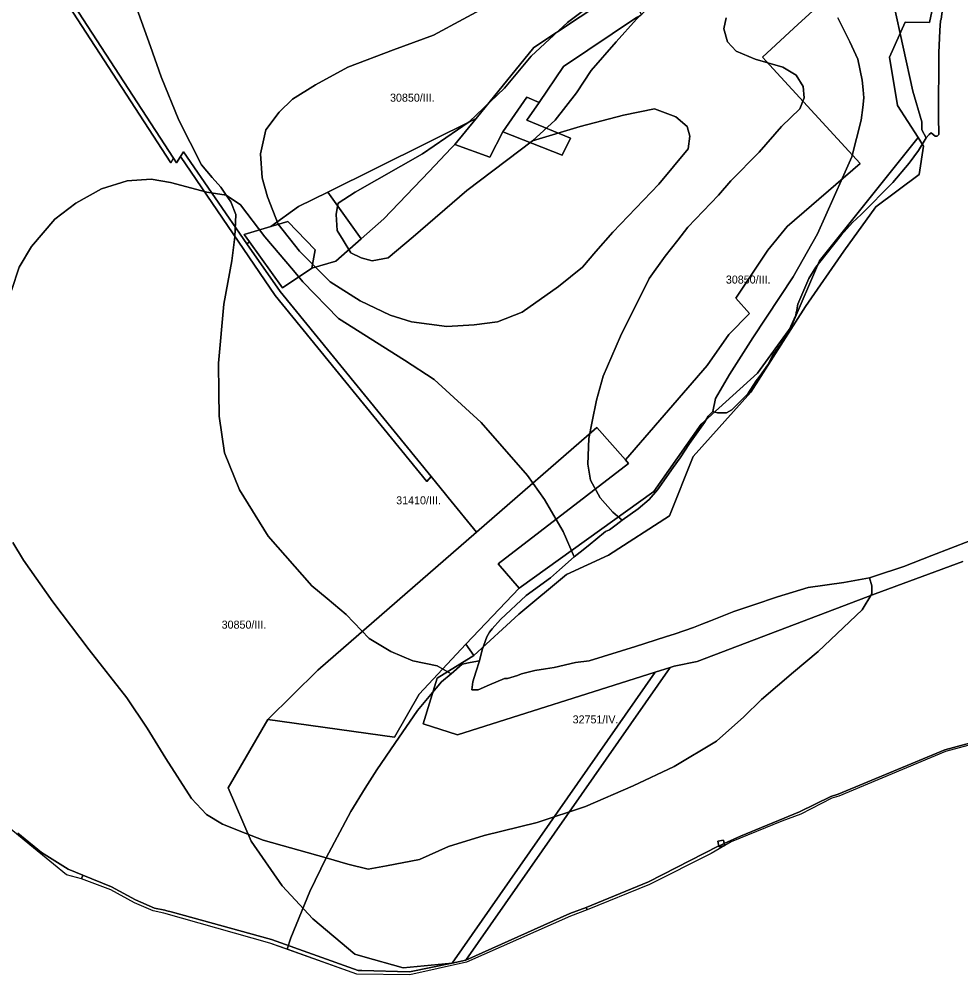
# Model space of a CAD drawing. Extents: x -541351 to -537540, y -1162694 to -1159725.
# Drawn here: x -538870 to -538281, y -1162694 to -1162097 of the extents above; entities that cross this region are included whole.
import ezdxf

# ---------------------------------------------------------------- set-up
doc = ezdxf.new("R2010")
doc.units = 0
for name, color, linetype in [('95560013', 7, 'Continuous'), ('95610013', 7, 'Continuous'), ('95620013', 7, 'Continuous'), ('95640013', 7, 'Continuous'), ('95660013', 7, 'Continuous')]:
    doc.layers.add(name, color=color, linetype=linetype)

msp = doc.modelspace()

# ---------------------------------------------------------------- linework, layer by layer
at = {"layer": '95560013'}
for points in [[(-538869.43, -1162041.03), (-538774.88, -1162186.74), (-538773.11, -1162183.87), (-538771.26, -1162186.72), (-538768.78, -1162182.83), (-538709.7, -1162269.66), (-538614.93, -1162385.76), (-538612.14, -1162382.82), (-538603.16, -1162393.83), (-538601.47, -1162395.9), (-538583.87, -1162417.45), (-538683.04, -1162503.68), (-538714.23, -1162534.51), (-538739.09, -1162577.31), (-538724.64, -1162610.63), (-538705.36, -1162638.6), (-538686.21, -1162659.05), (-538659.93, -1162681.21), (-538654.86, -1162682.65), (-538629.62, -1162689.8), (-538598.98, -1162686.73), (-538625.63, -1162692.31), (-538655.54, -1162691.51), (-538657.71, -1162691.45), (-538711.99, -1162672), (-538774.67, -1162654.78), (-538777.4, -1162654.03), (-538778.52, -1162653.72), (-538785.14, -1162652.4), (-538796.95, -1162647.2), (-538811.97, -1162639.05), (-538829.93, -1162631.77), (-538838.99, -1162628.1), (-538855.65, -1162617.58), (-538870.45, -1162605.67)], [(-538490.13, -1162076.14), (-538547.99, -1162114.54), (-538584.08, -1162158.95), (-538676.75, -1162205), (-538695.05, -1162214.09), (-538712.27, -1162226.46), (-538729.02, -1162231.4), (-538725.68, -1162236.09), (-538727.27, -1162237.23), (-538766.94, -1162179.94), (-538768.78, -1162182.83), (-538771.26, -1162186.72), (-538773.11, -1162183.87), (-538866.22, -1162040.39)], [(-538358.33, -1162077.66), (-538382.75, -1162100.13), (-538405.09, -1162120.69), (-538402.82, -1162123.17), (-538400.74, -1162125.44), (-538344.11, -1162187.17), (-538389.74, -1162226.5), (-538401.72, -1162241.28), (-538421.82, -1162271.38), (-538413.32, -1162280.83), (-538426.13, -1162294.07), (-538439.64, -1162313.45), (-538490.74, -1162372.39), (-538508.66, -1162352.04), (-538583.87, -1162417.45), (-538601.47, -1162395.9), (-538603.16, -1162393.83), (-538612.14, -1162382.82), (-538706.58, -1162267.12), (-538727.27, -1162237.23), (-538725.68, -1162236.09), (-538705.15, -1162264.89), (-538686.77, -1162252.58), (-538671.71, -1162248.06), (-538655.83, -1162234.14), (-538641.65, -1162221.7), (-538613.46, -1162192.15), (-538599.58, -1162177.6), (-538597.29, -1162175.19), (-538575.5, -1162183.26), (-538567.4, -1162167.24), (-538530.37, -1162181.9), (-538525.16, -1162171.29), (-538552.35, -1162160.1), (-538544.72, -1162148.92), (-538529.45, -1162126.6), (-538483.95, -1162095.95)], [(-538257.12, -1162544.31), (-538291.24, -1162553.47), (-538357.78, -1162581.24), (-538362.41, -1162582.63), (-538381.99, -1162592.28), (-538418.76, -1162607.46), (-538428.99, -1162612.1), (-538429.43, -1162610), (-538432.98, -1162610.67), (-538432.4, -1162613.64), (-538432.73, -1162613.79), (-538476.34, -1162636.06), (-538515.25, -1162652.09), (-538525.45, -1162655.75), (-538590.41, -1162684.93), (-538462.84, -1162502), (-538460.21, -1162501.17), (-538445.95, -1162498.39), (-538334.63, -1162456.04), (-538279.83, -1162435.82)]]:
    msp.add_lwpolyline(points, dxfattribs=at)
msp.add_lwpolyline([(-538432.4, -1162613.64), (-538432.98, -1162610.67), (-538429.43, -1162610), (-538428.99, -1162612.1)], close=True, dxfattribs=at)
at = {"layer": '95610013'}
msp.add_lwpolyline([(-538294.68, -1162070.18), (-538300.82, -1162098.99), (-538315.9, -1162098.85), (-538325.79, -1162120.61), (-538320.79, -1162150.88), (-538307.92, -1162170.92), (-538369.57, -1162247.97), (-538387.23, -1162289.19), (-538408.16, -1162318.09), (-538443.36, -1162349.97), (-538473.08, -1162392.14), (-538557.2, -1162452.57), (-538570.19, -1162437.29), (-538488.91, -1162374.62), (-538490.74, -1162372.39), (-538439.64, -1162313.45), (-538426.13, -1162294.07), (-538413.32, -1162280.83), (-538421.82, -1162271.38), (-538401.72, -1162241.28), (-538389.74, -1162226.5), (-538344.11, -1162187.17), (-538400.74, -1162125.44), (-538402.82, -1162123.17), (-538405.09, -1162120.69), (-538382.75, -1162100.13), (-538358.33, -1162077.66)], dxfattribs=at)
for points in [[(-538483.95, -1162095.95), (-538529.45, -1162126.6), (-538544.72, -1162148.92), (-538552.35, -1162145.62), (-538567.4, -1162167.24), (-538575.5, -1162183.26), (-538597.29, -1162175.19), (-538584.08, -1162158.95), (-538547.99, -1162114.54), (-538490.13, -1162076.14), (-538490, -1162076.05), (-538480.64, -1162094.32)], [(-538525.16, -1162171.29), (-538530.37, -1162181.9), (-538567.4, -1162167.24), (-538552.35, -1162145.62), (-538544.72, -1162148.92), (-538552.35, -1162160.1)], [(-538684.56, -1162241), (-538701.7, -1162223.35), (-538712.27, -1162226.46), (-538695.05, -1162214.09), (-538676.75, -1162205), (-538655.83, -1162234.14), (-538671.71, -1162248.06), (-538686.77, -1162252.58)], [(-538701.7, -1162223.35), (-538684.56, -1162241), (-538686.77, -1162252.58), (-538705.15, -1162264.89), (-538725.68, -1162236.09), (-538729.02, -1162231.4), (-538712.27, -1162226.46)], [(-538714.23, -1162534.51), (-538683.04, -1162503.68), (-538583.87, -1162417.45), (-538508.66, -1162352.04), (-538490.74, -1162372.39), (-538488.91, -1162374.62), (-538570.19, -1162437.29), (-538557.2, -1162452.57), (-538590.57, -1162487.53), (-538605.03, -1162503.02), (-538619.65, -1162518.68), (-538635.07, -1162545.65)], [(-538608.47, -1162508.72), (-538617.07, -1162537.21), (-538595.65, -1162544.21), (-538472.23, -1162504.99), (-538598.98, -1162686.73), (-538629.62, -1162689.8), (-538654.86, -1162682.65), (-538659.93, -1162681.21), (-538686.21, -1162659.05), (-538705.36, -1162638.6), (-538724.64, -1162610.63), (-538739.09, -1162577.31), (-538714.23, -1162534.51), (-538635.07, -1162545.65), (-538619.65, -1162518.68), (-538605.03, -1162503.02), (-538590.57, -1162487.53), (-538585.52, -1162494.51), (-538587.16, -1162495.52)]]:
    msp.add_lwpolyline(points, close=True, dxfattribs=at)
at = {"layer": '95620013'}
msp.add_lwpolyline([(-538279.83, -1162435.82), (-538334.63, -1162456.04), (-538445.95, -1162498.39), (-538460.21, -1162501.17), (-538462.84, -1162502), (-538472.23, -1162504.99), (-538595.65, -1162544.21), (-538617.07, -1162537.21), (-538608.47, -1162508.72), (-538587.16, -1162495.52), (-538585.52, -1162494.51), (-538557.31, -1162468.81), (-538527.65, -1162443.97), (-538501.37, -1162431.85), (-538463.24, -1162407.26), (-538448.5, -1162370.31), (-538412.3, -1162330.08), (-538378.23, -1162276.57), (-538354.34, -1162241.81), (-538334.23, -1162214.24), (-538307.2, -1162193.94), (-538304.48, -1162176.27), (-538307.92, -1162170.92), (-538320.79, -1162150.88), (-538325.79, -1162120.61), (-538315.9, -1162098.85), (-538300.82, -1162098.99), (-538294.68, -1162070.18)], dxfattribs=at)
for points in [[(-538584.08, -1162158.95), (-538597.29, -1162175.19), (-538599.58, -1162177.6), (-538613.46, -1162192.15), (-538641.65, -1162221.7), (-538655.83, -1162234.14), (-538676.75, -1162205)], [(-538557.31, -1162468.81), (-538585.52, -1162494.51), (-538590.57, -1162487.53), (-538557.2, -1162452.57), (-538473.08, -1162392.14), (-538443.36, -1162349.97), (-538408.16, -1162318.09), (-538387.23, -1162289.19), (-538369.57, -1162247.97), (-538307.92, -1162170.92), (-538304.48, -1162176.27), (-538307.2, -1162193.94), (-538334.23, -1162214.24), (-538354.34, -1162241.81), (-538378.23, -1162276.57), (-538412.3, -1162330.08), (-538448.5, -1162370.31), (-538463.24, -1162407.26), (-538501.37, -1162431.85), (-538527.65, -1162443.97)]]:
    msp.add_lwpolyline(points, close=True, dxfattribs=at)
at = {"layer": '95640013'}
for points in [[(-538774.88, -1162186.74), (-538869.43, -1162041.03), (-538866.22, -1162040.39), (-538773.11, -1162183.87)], [(-538706.58, -1162267.12), (-538612.14, -1162382.82), (-538614.93, -1162385.76), (-538709.7, -1162269.66), (-538768.78, -1162182.83), (-538766.94, -1162179.94), (-538727.27, -1162237.23)], [(-538462.84, -1162502), (-538590.41, -1162684.93), (-538598.98, -1162686.73), (-538472.23, -1162504.99)], [(-538432.4, -1162613.64), (-538432.29, -1162614.22), (-538428.73, -1162613.36), (-538432.09, -1162615.33), (-538437.2, -1162618.34), (-538475.64, -1162637.57), (-538514.72, -1162653.42), (-538515.25, -1162652.09), (-538476.34, -1162636.06), (-538432.73, -1162613.79)], [(-538428.99, -1162612.1), (-538428.73, -1162613.36), (-538432.29, -1162614.22), (-538432.4, -1162613.64)], [(-538514.72, -1162653.42), (-538525.11, -1162657.36), (-538589.99, -1162686.16), (-538625.49, -1162694.15), (-538658.52, -1162693.62), (-538712.88, -1162674.25), (-538779.19, -1162655.51), (-538785.91, -1162654.22), (-538797.48, -1162649.16), (-538812.4, -1162640.97), (-538830.6, -1162634.06), (-538829.93, -1162631.77), (-538811.97, -1162639.05), (-538796.95, -1162647.2), (-538785.14, -1162652.4), (-538778.52, -1162653.72), (-538777.4, -1162654.03), (-538774.67, -1162654.78), (-538711.99, -1162672), (-538657.71, -1162691.45), (-538655.54, -1162691.51), (-538625.63, -1162692.31), (-538598.98, -1162686.73), (-538590.41, -1162684.93), (-538525.45, -1162655.75), (-538515.25, -1162652.09)]]:
    msp.add_lwpolyline(points, close=True, dxfattribs=at)
for points in [[(-538256.67, -1162545.39), (-538290.71, -1162554.65), (-538357.43, -1162582.44), (-538361.85, -1162583.75), (-538381.21, -1162593.74), (-538393.08, -1162598.16), (-538424.63, -1162610.94), (-538428.73, -1162613.36), (-538428.99, -1162612.1), (-538418.76, -1162607.46), (-538381.99, -1162592.28), (-538362.41, -1162582.63), (-538357.78, -1162581.24), (-538291.24, -1162553.47), (-538257.12, -1162544.31)], [(-538870.45, -1162605.67), (-538855.65, -1162617.58), (-538838.99, -1162628.1), (-538829.93, -1162631.77), (-538830.6, -1162634.06), (-538840.06, -1162631.57), (-538848.15, -1162624.99), (-538862.99, -1162612.9), (-538874.92, -1162603.19)]]:
    msp.add_lwpolyline(points, dxfattribs=at)
at = {"layer": '95660013'}
for points in [[(-538485.62, -1162068), (-538526.87, -1162099), (-538549.69, -1162120), (-538566.31, -1162140), (-538588.5, -1162161), (-538617.5, -1162181), (-538659.69, -1162205), (-538670.19, -1162212), (-538670.83, -1162215.11), (-538671.62, -1162219), (-538670.81, -1162229), (-538667.12, -1162235), (-538662.31, -1162243), (-538655.87, -1162246), (-538649.12, -1162248), (-538639.12, -1162246), (-538623.37, -1162233), (-538589.87, -1162204), (-538548.81, -1162173), (-538519.12, -1162164), (-538492, -1162157), (-538472.62, -1162153), (-538459.37, -1162158), (-538452.12, -1162164), (-538450.5, -1162170), (-538451.62, -1162178), (-538469.87, -1162200), (-538498.62, -1162230), (-538509.21, -1162242.22), (-538517.69, -1162252), (-538532.62, -1162264), (-538555.31, -1162280), (-538570.81, -1162286), (-538585.19, -1162288), (-538602.37, -1162289), (-538624.5, -1162286), (-538637.81, -1162282), (-538656.62, -1162273), (-538675.37, -1162261), (-538694.5, -1162242), (-538707.81, -1162225), (-538714.37, -1162208), (-538717.81, -1162196), (-538718.81, -1162181), (-538715.5, -1162166), (-538707.19, -1162155), (-538698.87, -1162147), (-538684.5, -1162138), (-538664.31, -1162127), (-538635.62, -1162116), (-538610.69, -1162107), (-538573.62, -1162087)], [(-538468.19, -1162082), (-538483.81, -1162097), (-538496.62, -1162111), (-538512.12, -1162129), (-538521.31, -1162143), (-538534.62, -1162160), (-538548.81, -1162173), (-538589.87, -1162204), (-538623.37, -1162233), (-538639.12, -1162246), (-538649.12, -1162248), (-538655.87, -1162246), (-538662.31, -1162243), (-538667.12, -1162235), (-538670.81, -1162229), (-538671.62, -1162219), (-538670.83, -1162215.11), (-538670.19, -1162212), (-538659.69, -1162205), (-538617.5, -1162181), (-538588.5, -1162161), (-538566.31, -1162140), (-538549.69, -1162120), (-538526.87, -1162099), (-538485.62, -1162068)], [(-538573.62, -1162087), (-538610.69, -1162107), (-538635.62, -1162116), (-538664.31, -1162127), (-538684.5, -1162138), (-538698.87, -1162147), (-538707.19, -1162155), (-538715.5, -1162166), (-538718.81, -1162181), (-538717.81, -1162196), (-538714.37, -1162208), (-538707.81, -1162225), (-538694.5, -1162242), (-538675.37, -1162261), (-538656.62, -1162273), (-538637.81, -1162282), (-538624.5, -1162286), (-538602.37, -1162289), (-538585.19, -1162288), (-538570.81, -1162286), (-538555.31, -1162280), (-538532.62, -1162264), (-538517.69, -1162252), (-538509.21, -1162242.22), (-538498.62, -1162230), (-538469.87, -1162200), (-538451.62, -1162178), (-538450.5, -1162170), (-538452.12, -1162164), (-538459.37, -1162158), (-538472.62, -1162153), (-538492, -1162157), (-538519.12, -1162164), (-538548.81, -1162173), (-538534.62, -1162160), (-538521.31, -1162143), (-538512.12, -1162129), (-538496.62, -1162111), (-538483.81, -1162097), (-538468.19, -1162082)], [(-538797, -1162088), (-538787.62, -1162114), (-538780.87, -1162133), (-538769.87, -1162160), (-538755.62, -1162188), (-538748.99, -1162195.78), (-538743.69, -1162202), (-538740.31, -1162207), (-538752.31, -1162205), (-538775, -1162199), (-538787.19, -1162197), (-538802.12, -1162198), (-538818.12, -1162203), (-538834.19, -1162212), (-538847.37, -1162222), (-538861.87, -1162239), (-538869.62, -1162252), (-538874.38, -1162266.44)], [(-538427.81, -1162096), (-538429.31, -1162103), (-538427, -1162111), (-538421.62, -1162117), (-538409.62, -1162122), (-538392.31, -1162127), (-538384.12, -1162132), (-538379.62, -1162139), (-538379.12, -1162146), (-538381.87, -1162153), (-538393.31, -1162164), (-538407.19, -1162180), (-538425, -1162198), (-538432.69, -1162207), (-538451.69, -1162227), (-538457.99, -1162235), (-538465.87, -1162245), (-538476, -1162259), (-538493.87, -1162295), (-538504.62, -1162320), (-538508.87, -1162335), (-538511.55, -1162348.33), (-538513.69, -1162359), (-538514.31, -1162375), (-538512.62, -1162385), (-538506.62, -1162396), (-538498.62, -1162405), (-538492.87, -1162410), (-538496.62, -1162413), (-538500.69, -1162416), (-538503.12, -1162417), (-538509.31, -1162422), (-538512.81, -1162425), (-538514, -1162426), (-538519, -1162430), (-538522.87, -1162433), (-538529.62, -1162417), (-538541.31, -1162397), (-538551.87, -1162382), (-538580.87, -1162349), (-538610.37, -1162322), (-538628.87, -1162310), (-538670.12, -1162284), (-538692.37, -1162261), (-538698.12, -1162254), (-538716, -1162233), (-538731.31, -1162213), (-538740.31, -1162207), (-538743.69, -1162202), (-538748.99, -1162195.78), (-538755.62, -1162188), (-538769.87, -1162160), (-538780.87, -1162133), (-538787.62, -1162114), (-538797, -1162088)], [(-538275.5, -1162423), (-538299.37, -1162432), (-538316.81, -1162439), (-538335.12, -1162445), (-538338.31, -1162446), (-538354.31, -1162449), (-538376.62, -1162452), (-538395.81, -1162458), (-538410.5, -1162463), (-538423, -1162467), (-538437.62, -1162473), (-538443.12, -1162475), (-538448.31, -1162477), (-538459.62, -1162481), (-538465.81, -1162483), (-538484.37, -1162489), (-538513.37, -1162498), (-538521.87, -1162499), (-538535.31, -1162502), (-538540.81, -1162503), (-538547.37, -1162504), (-538555.62, -1162506), (-538558.12, -1162507), (-538564.37, -1162509), (-538566.37, -1162509), (-538575.81, -1162513), (-538582.87, -1162516), (-538584.69, -1162516), (-538586.81, -1162516), (-538586.12, -1162511), (-538584.31, -1162505), (-538581.87, -1162498), (-538580.37, -1162491), (-538577.37, -1162483), (-538575.62, -1162480), (-538574.12, -1162478), (-538568.87, -1162472), (-538552.81, -1162457), (-538537.69, -1162446), (-538532, -1162441), (-538522.87, -1162433), (-538519, -1162430), (-538514, -1162426), (-538512.81, -1162425), (-538509.31, -1162422), (-538503.12, -1162417), (-538500.69, -1162416), (-538496.62, -1162413), (-538492.87, -1162410), (-538482.87, -1162403), (-538476, -1162397), (-538470.81, -1162391), (-538460.87, -1162377), (-538456.5, -1162371), (-538450.69, -1162362), (-538446.55, -1162356.22), (-538441.37, -1162349), (-538439.12, -1162345), (-538436.19, -1162342), (-538433.31, -1162343), (-538430.12, -1162343), (-538427.62, -1162343), (-538424.31, -1162341), (-538414.37, -1162331), (-538409, -1162323), (-538406.69, -1162320), (-538401.81, -1162313), (-538398.69, -1162307), (-538393.69, -1162300), (-538391.33, -1162296), (-538388.37, -1162291), (-538384.37, -1162282), (-538383.99, -1162280.33), (-538383.69, -1162279), (-538383.44, -1162277.22), (-538383.12, -1162275), (-538376.12, -1162259), (-538371.81, -1162252), (-538365.62, -1162244), (-538355.87, -1162232), (-538348.81, -1162224), (-538343.37, -1162219), (-538323.62, -1162199), (-538313.37, -1162187), (-538307.62, -1162179), (-538302.87, -1162171), (-538301, -1162169), (-538299.62, -1162168), (-538297.31, -1162170), (-538296, -1162170), (-538294.87, -1162169), (-538295.12, -1162158), (-538294.87, -1162118), (-538294.37, -1162104), (-538293.87, -1162098), (-538293.37, -1162097), (-538292, -1162086)], [(-538323.31, -1162087), (-538311.12, -1162142), (-538305.62, -1162161), (-538305.62, -1162166), (-538302.87, -1162171), (-538307.62, -1162179), (-538313.37, -1162187), (-538323.62, -1162199), (-538343.37, -1162219), (-538348.81, -1162224), (-538355.87, -1162232), (-538365.62, -1162244), (-538371.81, -1162252), (-538376.12, -1162259), (-538383.12, -1162275), (-538383.44, -1162277.22), (-538383.69, -1162279), (-538383.99, -1162280.33), (-538384.37, -1162282), (-538388.37, -1162291), (-538391.33, -1162296), (-538393.69, -1162300), (-538398.69, -1162307), (-538401.81, -1162313), (-538406.69, -1162320), (-538409, -1162323), (-538414.37, -1162331), (-538424.31, -1162341), (-538427.62, -1162343), (-538430.12, -1162343), (-538433.31, -1162343), (-538436.19, -1162342), (-538434.5, -1162334), (-538425.81, -1162319), (-538411.12, -1162296), (-538385.87, -1162258), (-538370.81, -1162231), (-538355.12, -1162196), (-538349.37, -1162183), (-538343.37, -1162160), (-538342.44, -1162152.22), (-538341.69, -1162146), (-538342.21, -1162141.11), (-538342.87, -1162135), (-538345.5, -1162122), (-538350.62, -1162111), (-538358, -1162096)], [(-538292, -1162086), (-538293.37, -1162097), (-538293.87, -1162098), (-538294.37, -1162104), (-538294.87, -1162118), (-538295.12, -1162158), (-538294.87, -1162169), (-538296, -1162170), (-538297.31, -1162170), (-538299.62, -1162168), (-538301, -1162169), (-538302.87, -1162171), (-538305.62, -1162166), (-538305.62, -1162161), (-538311.12, -1162142), (-538323.31, -1162087)], [(-538358, -1162096), (-538350.62, -1162111), (-538345.5, -1162122), (-538342.87, -1162135), (-538342.21, -1162141.11), (-538341.69, -1162146), (-538342.44, -1162152.22), (-538343.37, -1162160), (-538349.37, -1162183), (-538355.12, -1162196), (-538370.81, -1162231), (-538385.87, -1162258), (-538411.12, -1162296), (-538425.81, -1162319), (-538434.5, -1162334), (-538436.19, -1162342), (-538439.12, -1162345), (-538441.37, -1162349), (-538446.55, -1162356.22), (-538450.69, -1162362), (-538456.5, -1162371), (-538460.87, -1162377), (-538470.81, -1162391), (-538476, -1162397), (-538482.87, -1162403), (-538492.87, -1162410), (-538498.62, -1162405), (-538506.62, -1162396), (-538512.62, -1162385), (-538514.31, -1162375), (-538513.69, -1162359), (-538511.55, -1162348.33), (-538508.87, -1162335), (-538504.62, -1162320), (-538493.87, -1162295), (-538476, -1162259), (-538465.87, -1162245), (-538457.99, -1162235), (-538451.69, -1162227), (-538432.69, -1162207), (-538425, -1162198), (-538407.19, -1162180), (-538393.31, -1162164), (-538381.87, -1162153), (-538379.12, -1162146), (-538379.62, -1162139), (-538384.12, -1162132), (-538392.31, -1162127), (-538409.62, -1162122), (-538421.62, -1162117), (-538427, -1162111), (-538429.31, -1162103), (-538427.81, -1162096)], [(-538874.38, -1162266.44), (-538869.62, -1162252), (-538861.87, -1162239), (-538847.37, -1162222), (-538834.19, -1162212), (-538818.12, -1162203), (-538802.12, -1162198), (-538787.19, -1162197), (-538775, -1162199), (-538752.31, -1162205), (-538740.31, -1162207), (-538737.37, -1162211), (-538734.12, -1162219), (-538734.87, -1162233), (-538736.62, -1162248), (-538741.81, -1162275), (-538745.12, -1162312), (-538744.88, -1162330.33), (-538744.69, -1162345), (-538741.31, -1162368), (-538731.87, -1162391), (-538714, -1162420), (-538686.69, -1162451), (-538677.21, -1162459), (-538665.37, -1162469), (-538650.87, -1162484), (-538637.31, -1162492), (-538623.62, -1162498), (-538608.31, -1162501), (-538599.69, -1162506), (-538605.69, -1162511), (-538612.33, -1162519), (-538620.62, -1162529), (-538634.83, -1162549.56), (-538646.19, -1162566), (-538653.38, -1162577.56), (-538662.37, -1162592), (-538677.81, -1162621), (-538717.19, -1162610), (-538728.49, -1162605.56), (-538742.62, -1162600), (-538752.62, -1162594), (-538762, -1162584), (-538778, -1162559), (-538789.62, -1162540), (-538802.37, -1162521), (-538825.87, -1162491), (-538848.62, -1162461), (-538866.81, -1162435), (-538873.5, -1162424)], [(-538256.67, -1162545.39), (-538290.71, -1162554.65), (-538357.43, -1162582.44), (-538361.85, -1162583.75), (-538381.21, -1162593.74), (-538393.08, -1162598.16), (-538424.63, -1162610.94), (-538428.73, -1162613.36), (-538432.09, -1162615.33), (-538437.2, -1162618.34), (-538475.64, -1162637.57), (-538514.72, -1162653.42), (-538525.11, -1162657.36), (-538589.99, -1162686.16), (-538625.49, -1162694.15), (-538658.52, -1162693.62), (-538702.19, -1162678.06), (-538699.87, -1162671), (-538688, -1162642), (-538677.81, -1162621), (-538664.31, -1162625), (-538651.62, -1162628), (-538640, -1162626), (-538619.5, -1162622), (-538601.31, -1162614), (-538579.12, -1162607), (-538545.87, -1162599), (-538515.81, -1162589), (-538485.87, -1162576), (-538460.37, -1162564), (-538433.87, -1162548), (-538416.81, -1162533), (-538405.69, -1162522), (-538385.81, -1162505), (-538370.31, -1162492), (-538342.87, -1162466), (-538336.81, -1162456), (-538336.81, -1162451), (-538338.31, -1162446), (-538335.12, -1162445), (-538316.81, -1162439), (-538299.37, -1162432), (-538275.5, -1162423)], [(-538873.5, -1162424), (-538866.81, -1162435), (-538848.62, -1162461), (-538825.87, -1162491), (-538802.37, -1162521), (-538789.62, -1162540), (-538778, -1162559), (-538762, -1162584), (-538752.62, -1162594), (-538742.62, -1162600), (-538728.49, -1162605.56), (-538717.19, -1162610), (-538677.81, -1162621), (-538688, -1162642), (-538699.87, -1162671), (-538702.19, -1162678.06), (-538712.88, -1162674.25), (-538779.19, -1162655.51), (-538785.91, -1162654.22), (-538797.48, -1162649.16), (-538812.4, -1162640.97), (-538830.6, -1162634.06), (-538840.06, -1162631.57), (-538848.15, -1162624.99), (-538862.99, -1162612.9), (-538874.92, -1162603.19)]]:
    msp.add_lwpolyline(points, dxfattribs=at)
for points in [[(-538522.87, -1162433), (-538532, -1162441), (-538537.69, -1162446), (-538552.81, -1162457), (-538568.87, -1162472), (-538574.12, -1162478), (-538575.62, -1162480), (-538577.37, -1162483), (-538580.37, -1162491), (-538581.87, -1162498), (-538587.81, -1162499), (-538592.87, -1162500), (-538599.69, -1162506), (-538608.31, -1162501), (-538623.62, -1162498), (-538637.31, -1162492), (-538650.87, -1162484), (-538665.37, -1162469), (-538677.21, -1162459), (-538686.69, -1162451), (-538714, -1162420), (-538731.87, -1162391), (-538741.31, -1162368), (-538744.69, -1162345), (-538744.88, -1162330.33), (-538745.12, -1162312), (-538741.81, -1162275), (-538736.62, -1162248), (-538734.87, -1162233), (-538734.12, -1162219), (-538737.37, -1162211), (-538740.31, -1162207), (-538731.31, -1162213), (-538716, -1162233), (-538698.12, -1162254), (-538692.37, -1162261), (-538670.12, -1162284), (-538628.87, -1162310), (-538610.37, -1162322), (-538580.87, -1162349), (-538551.87, -1162382), (-538541.31, -1162397), (-538529.62, -1162417)], [(-538677.81, -1162621), (-538662.37, -1162592), (-538653.38, -1162577.56), (-538646.19, -1162566), (-538634.83, -1162549.56), (-538620.62, -1162529), (-538612.33, -1162519), (-538605.69, -1162511), (-538599.69, -1162506), (-538592.87, -1162500), (-538587.81, -1162499), (-538581.87, -1162498), (-538584.31, -1162505), (-538586.12, -1162511), (-538586.81, -1162516), (-538584.69, -1162516), (-538582.87, -1162516), (-538575.81, -1162513), (-538566.37, -1162509), (-538564.37, -1162509), (-538558.12, -1162507), (-538555.62, -1162506), (-538547.37, -1162504), (-538540.81, -1162503), (-538535.31, -1162502), (-538521.87, -1162499), (-538513.37, -1162498), (-538484.37, -1162489), (-538465.81, -1162483), (-538459.62, -1162481), (-538448.31, -1162477), (-538443.12, -1162475), (-538437.62, -1162473), (-538423, -1162467), (-538410.5, -1162463), (-538395.81, -1162458), (-538376.62, -1162452), (-538354.31, -1162449), (-538338.31, -1162446), (-538336.81, -1162451), (-538336.81, -1162456), (-538342.87, -1162466), (-538370.31, -1162492), (-538385.81, -1162505), (-538405.69, -1162522), (-538416.81, -1162533), (-538433.87, -1162548), (-538460.37, -1162564), (-538485.87, -1162576), (-538515.81, -1162589), (-538545.87, -1162599), (-538579.12, -1162607), (-538601.31, -1162614), (-538619.5, -1162622), (-538640, -1162626), (-538651.62, -1162628), (-538664.31, -1162625)]]:
    msp.add_lwpolyline(points, close=True, dxfattribs=at)

# ---------------------------------------------------------------- texts
for s, rotation, p in [('30850/III.', 0, (-538637.86, -1162148.5)), ('30850/III.', 360, (-538428, -1162262.15)), ('31410/III.', 0, (-538634, -1162400.11)), ('30850/III.', 0, (-538743.09, -1162477.78)), ('32751/IV.', 360, (-538523.75, -1162537))]:
    msp.add_text(s, height=5, rotation=rotation, dxfattribs=at).set_placement(p)

doc.saveas('drawing.dxf')
